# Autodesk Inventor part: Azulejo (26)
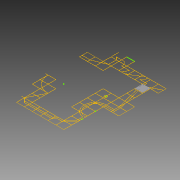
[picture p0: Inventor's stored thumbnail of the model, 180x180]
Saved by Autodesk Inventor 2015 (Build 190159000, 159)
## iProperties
Created: 2015-04
Part Number: Azulejo (26)
Material: Genérico
Document SubType Name: Modeling
Designer: Felipe
Density: 1 g/cm^3
Appearance: Padrão
Author: Felipe
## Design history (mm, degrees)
sketch "Sketch1"
  geometry: L1 (-1510, -7490)-(-1510, -6010); L2 (992.445, 7510)-(992.445, 8990); L3 (1012.445, 7510)-(1012.445, 8990); L4 (-3010, -1490)-(-3010, -10); L5 (-1510, 7490)-(-2990, 7490); L6 (-2990, 10)-(-1510, 10); L7 (-1510, -10)-(-2990, -10); L8 (-1510, -1490)-(-1510, -10); L9 (-10, 9010)-(-10, 10490); L10 (-10, 7510)-(-10, 8990); L11 (-10, 7490)-(-1490, 7490); L12 (-1490, 6010)-(-10, 6010); L13 (-10, 5990)-(-1490, 5990); L14 (-1490, -10)-(-1490, -1490); L15 (-1490, -1490)-(-10, -1490); L16 (-10, -1510)-(-1490, -1510); L17 (-10, -2990)-(-10, -1510); L18 (-10, -5990)-(-10, -4510); L19 (-1490, -7490)-(-10, -7490); L20 (10, 8990)-(10, 7510); L21 (1490, 7510)-(1490, 8990); L22 (10, 6010)-(1490, 6010); L23 (1490, 6010)-(1490, 7490); L24 (1490, 5990)-(10, 5990); L25 (4490, -6010)-(3010, -6010); L26 (10, -1510)-(10, -2990); L27 (10, -3010)-(10, -4490); L28 (10, -4510)-(10, -5990); L29 (10, -5990)-(1490, -5990); L30 (1490, -6010)-(10, -6010); L31 (10, -7490)-(1490, -7490); L32 (2990, 9010)-(2990, 10490); L33 (1510, 8990)-(1510, 7510); L34 (1510, 7510)-(2990, 7510); L35 (2990, 7490)-(1510, 7490); L36 (1510, 7490)-(1510, 6010); L37 (1510, -5990)-(2990, -5990); L38 (2990, -6010)-(1510, -6010); L39 (1510, -7490)-(2990, -7490); L40 (3010, 10490)-(3010, 9010); L41 (3010, 9010)-(4490, 9010); L42 (4490, 8990)-(3010, 8990); L43 (4490, 7490)-(3010, 7490); L44 (4490, 1510)-(4490, 2990); L45 (4490, 10)-(4490, 1490); L46 (4490, -1490)-(4490, -10); L47 (4490, -2990)-(4490, -1510); L48 (3010, -5990)-(4490, -5990); L49 (3010, -7490)-(4490, -7490); L50 (4510, 9010)-(5990, 9010); L51 (5990, 8990)-(4510, 8990); L52 (4510, 7510)-(5990, 7510); L53 (5990, 7490)-(4510, 7490); L54 (4510, 3010)-(5990, 3010); L55 (5990, 2990)-(4510, 2990); L56 (4510, 2990)-(4510, 1510); L57 (4510, 1510)-(5990, 1510); L58 (5990, 1510)-(5990, 1740.185); L59 (5990, 1760.2)-(5990, 2259.8); L60 (5990, 2279.815)-(5990, 2990); L61 (5990, 1490)-(4510, 1490); L62 (4510, 1490)-(4510, 10); L63 (4510, 10)-(5990, 10); L64 (5990, 10)-(5990, 1490)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; A1 r 250 centre (6000, 2010) between (5990, 2259.8) and (5990, 1760.2); A2 r 250 centre (6000, 2010) between (6010, 1760.2) and (6010, 2259.8); A3 r 270 centre (6000, 2010) between (5990, 2279.815) and (5990, 1740.185); A4 r 270 centre (6000, 2010) between (6010, 1740.185) and (6010, 2279.815); A5 r 3010.017 centre (0, 0) between (-1490, -2615.358) and (-346.554, -2990); A6 r 2990.017 centre (0, 0) between (-1490, -2592.316) and (-10, -2990); A7 r 3010.017 centre (0, 0) between (-2603.863, -1510) and (-1510, -2603.863); A8 r 2990.017 centre (0, 0) between (-2580.717, -1510) and (-1510, -2580.717); A9 r 3010.017 centre (0, 0) between (-2990, -346.554) and (-2615.358, -1490); A10 r 2990.017 centre (0, 0) between (-2990, -10) and (-2592.316, -1490); A11 r 2131.367 centre (7500, -1500) between (7490, 631.344) and (6010, 24.017); A12 r 2131.367 centre (7500, -1500) between (5975.983, -10) and (5368.656, -1490); A13 r 2131.367 centre (7500, -1500) between (5368.656, -1510) and (5975.983, -2990); A14 r 2131.367 centre (7500, -1500) between (6010, -3024.017) and (7190, -3608.703); A15 r 1831.367 centre (7500, -1500) between (7490.321, 331.342) and (6463.753, 10); A16 r 1831.367 centre (7500, -1500) between (6435.196, -10) and (6010, -435.196); A17 r 1831.367 centre (7500, -1500) between (5990, -463.753) and (5668.66, -1490); A18 r 1831.367 centre (7500, -1500) between (5668.66, -1510) and (5990, -2536.247); A19 r 1831.367 centre (7500, -1500) between (6010, -2564.804) and (6435.196, -2990); A20 r 1831.367 centre (7500, -1500) between (6463.753, -3010) and (7490, -3331.34); A21 r 2111.367 centre (7500, -1500) between (7490.047, 611.344) and (6024.272, 10); A22 r 2111.367 centre (7500, -1500) between (5990, -24.272) and (5388.656, -1490); A23 r 2111.367 centre (7500, -1500) between (5388.656, -1510) and (5990, -2975.728); A24 r 2111.367 centre (7500, -1500) between (6024.272, -3010) and (7210, -3591.357); A25 r 1811.367 centre (7500, -1500) between (7490.374, 311.342) and (6499.524, 10); A26 r 1811.367 centre (7500, -1500) between (6469.975, -10) and (6010, -469.975); A27 r 1811.367 centre (7500, -1500) between (5990, -499.524) and (5688.66, -1490); A28 r 1811.367 centre (7500, -1500) between (5688.66, -1510) and (5990, -2500.476); A29 r 1811.367 centre (7500, -1500) between (6010, -2530.025) and (6469.975, -2990); A30 r 1811.367 centre (7500, -1500) between (6499.524, -3010) and (7490, -3311.34); A31 r 449.871 centre (7499.449, -4060.672) between (7510, -4510.419) and (7521.546, -4510); A32 r 250 centre (6000, 2010) between (5990, 2259.8) and (5990, 1760.2); A33 r 250 centre (6000, 2010) between (6010, 1760.2) and (6010, 2259.8); A34 r 270 centre (6000, 2010) between (5990, 2279.815) and (5990, 1740.185); A35 r 270 centre (6000, 2010) between (6010, 1740.185) and (6010, 2279.815); A36 r 3010.017 centre (0, 0) between (-1490, -2615.358) and (-346.554, -2990); A37 r 2990.017 centre (0, 0) between (-1490, -2592.316) and (-10, -2990); A38 r 3010.017 centre (0, 0) between (-2603.863, -1510) and (-1510, -2603.863); A39 r 2990.017 centre (0, 0) between (-2580.717, -1510) and (-1510, -2580.717); A40 r 3010.017 centre (0, 0) between (-2990, -346.554) and (-2615.358, -1490); A41 r 2990.017 centre (0, 0) between (-2990, -10) and (-2592.316, -1490); A42 r 2131.367 centre (7500, -1500) between (7490, 631.344) and (6010, 24.017); A43 r 2131.367 centre (7500, -1500) between (5975.983, -10) and (5368.656, -1490); A44 r 2131.367 centre (7500, -1500) between (5368.656, -1510) and (5975.983, -2990); A45 r 2131.367 centre (7500, -1500) between (6010, -3024.017) and (7190, -3608.703); A46 r 1831.367 centre (7500, -1500) between (7490.321, 331.342) and (6463.753, 10); A47 r 1831.367 centre (7500, -1500) between (6435.196, -10) and (6010, -435.196); A48 r 1831.367 centre (7500, -1500) between (5990, -463.753) and (5668.66, -1490); A49 r 1831.367 centre (7500, -1500) between (5668.66, -1510) and (5990, -2536.247); A50 r 1831.367 centre (7500, -1500) between (6010, -2564.804) and (6435.196, -2990); A51 r 1831.367 centre (7500, -1500) between (6463.753, -3010) and (7490, -3331.34); A52 r 2111.367 centre (7500, -1500) between (7490.047, 611.344) and (6024.272, 10); A53 r 2111.367 centre (7500, -1500) between (5990, -24.272) and (5388.656, -1490); A54 r 2111.367 centre (7500, -1500) between (5388.656, -1510) and (5990, -2975.728); A55 r 2111.367 centre (7500, -1500) between (6024.272, -3010) and (7210, -3591.357); A56 r 1811.367 centre (7500, -1500) between (7490.374, 311.342) and (6499.524, 10); A57 r 1811.367 centre (7500, -1500) between (6469.975, -10) and (6010, -469.975); A58 r 1811.367 centre (7500, -1500) between (5990, -499.524) and (5688.66, -1490); A59 r 1811.367 centre (7500, -1500) between (5688.66, -1510) and (5990, -2500.476); A60 r 1811.367 centre (7500, -1500) between (6010, -2530.025) and (6469.975, -2990); A61 r 1811.367 centre (7500, -1500) between (6499.524, -3010) and (7490, -3311.34); A62 r 449.871 centre (7499.449, -4060.672) between (7510, -4510.419) and (7521.546, -4510); 15 further points
  constraints: 2084 end point, 128 point on circle, 62 centre point, 26 point on line, 2 horizontal, 2 other
extrude "Extrusion1" new body sketch "Sketch1" distance "d0" = 60; taper "d1" = 0 deg
extrude "Extrusion2" new body sketch "Sketch1" distance "d2" = 60; taper "d3" = 0 deg
extrude "Extrusion3" new body sketch "Sketch1" distance "d4" = 60; taper "d5" = 0 deg
body "Solid1"
body "Solid2"
body "Solid3"
